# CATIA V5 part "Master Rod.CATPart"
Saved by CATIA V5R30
Part number: Master Rod
Bounding box of the stored display mesh (mm): x -55.99 to 55.99, y -51.999 to 267.322, z -35 to 35
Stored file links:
  D:\PROJECTS\CATIA V56R 2020\Resources\Parts File\c12_catia_v5_6r2020_prt\c12_catia_v5-6r2020 figr_12-26\Master Rod.CATPart
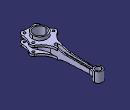
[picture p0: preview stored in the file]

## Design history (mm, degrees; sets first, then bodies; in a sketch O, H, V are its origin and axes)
Body1 (main body)
  Sketch1 on xy-plane, origin (0, 0, 0), H (1, 0, 0), V (0, 1, 0)
    arc A1 centre (0, 0) radius 31.5 from (-26.3425, 17.272) to (26.3425, 17.272) ccw
    arc A2 centre (0, 250) radius 17.5 from (14.7398, 240.5666) to (-14.7398, 240.5666) ccw
    point P1 (0, 250)
    line L1 (9, 220) -> (13, 60)
    point P2 (9, 220)
    point P3 (13, 60)
    arc A3 centre (94.6219, 62.0405) radius 81.6474 from (13, 60) to (26.3425, 17.272) ccw
    point P5 (26.3425, 17.272)
    arc A4 centre (45.4514, 220.9113) radius 36.4628 from (9, 220) to (14.7398, 240.5666) cw
    point P7 (14.7398, 240.5666)
    point P8 (-14.7398, 240.5666)
    point P9 (-9, 220)
    arc A5 centre (-45.4514, 220.9113) radius 36.4628 from (-9, 220) to (-14.7398, 240.5666) ccw
    point P11 (-13, 60)
    line L2 (-9, 220) -> (-13, 60)
    point P12 (-26.3425, 17.272)
    arc A6 centre (-94.6219, 62.0405) radius 81.6474 from (-13, 60) to (-26.3425, 17.272) cw
    radius A1 = 31.5
    radius A2 = 17.5
    distance P1 H = 250
    distance V P3 = 13
    distance P2 V = 9
    distance P1 P2 V = 30
    distance P3 P2 V = 160
    coincidence: P1 V
    tangency: A3 L1, A3 A1, A4 L1, A4 A2
    symmetry: P7 P8 V, P2 P9 V, A4 A5 V, P3 P11 V, L1 L2 V, P5 P12 V, A3 A6 V
  Pad1: profile Sketch1, direction (0, 0, 1), length 21, mirrored extent
  Sketch2 on face of Pad1, origin (0, 0, 21), H (1, 0, 0), V (0, 1, 0)
    point P1 (43, 16)
    point P2 (26, -39)
    arc A1 centre (43, 16) radius 13 from (53.3864, 8.1819) to (49.3111, 27.3653) ccw
    arc A2 centre (26, -39) radius 13 from (22.0235, -51.3769) to (38.9864, -38.4063) ccw
    reference projected line E1 (9, 220) -> (12.2872, 88.5122) from edge of Pad1
    arc A3 centre (84.2647, 90.3117) radius 72 from (49.3111, 27.3653) to (12.2872, 88.5122) cw
    point P5 (49.3111, 27.3653)
    point P6 (12.2872, 88.5122)
    arc A4 centre (110.9113, -35.118) radius 72 from (38.9864, -38.4063) to (53.3864, 8.1819) cw
    point P8 (38.9864, -38.4063)
    point P9 (53.3864, 8.1819)
    point P10 (-12.2872, 88.5122)
    point P11 (-49.3111, 27.3653)
    arc A5 centre (-84.2647, 90.3117) radius 72 from (-49.3111, 27.3653) to (-12.2872, 88.5122) ccw
    point P13 (-53.3864, 8.1819)
    arc A6 centre (-43, 16) radius 13 from (-53.3864, 8.1819) to (-49.3111, 27.3653) cw
    point P15 (-38.9864, -38.4063)
    arc A7 centre (-110.9113, -35.118) radius 72 from (-38.9864, -38.4063) to (-53.3864, 8.1819) ccw
    arc A8 centre (-26, -39) radius 13 from (-22.0235, -51.3769) to (-38.9864, -38.4063) cw
    line L1 (12.2872, 88.5122) -> (-12.2872, 88.5122)
    arc A9 centre (0, -119.9259) radius 72 from (-22.0235, -51.3769) to (22.0235, -51.3769) cw
    distance V P2 = 26
    distance P2 P1 H = 17
    distance P1 P2 V = 55
    distance P2 H = 39
    radius A1 = 13
    radius A2 = 13
    radius A3 = 72
    radius A4 = 72
    radius A9 = 72
    tangency: A3 E1, A3 A1, A4 A1, A4 A2, A9 A8, A9 A2
    symmetry: P6 P10 V, P5 P11 V, A3 A5 V, P9 P13 V, A1 A6 V, P8 P15 V, A4 A7 V, A2 A8 V
    horizontal: L1 H
  Pad2: profile Sketch2, direction (0, 0, -1), length 9
  Mirror1: of Pad2, Sketch2, about xy-plane
  Sketch3 on xy-plane, origin (0, 0, 0), H (1, 0, 0), V (0, 1, 0)
    circle A1 centre (0, 0) radius 31.5
    reference projected arc E1 centre (0, 0) radius 31.5 from (-26.3425, 17.272) to (26.3425, 17.272) ccw from edge of Pad2
    tangency: A1 E1
  Pad3: profile Sketch3, direction (0, 0, 1), length 35, mirrored extent
  Sketch4 on xy-plane, origin (0, 0, 0), H (1, 0, 0), V (0, 1, 0)
    circle A1 centre (0, 0) radius 26
    circle A2 centre (43, 16) radius 5
    circle A3 centre (26, -39) radius 5
    reference projected arc E1 centre (43, 16) radius 13 from (53.3864, 8.1819) to (49.3111, 27.3653) ccw from edge of Pad2
    reference projected arc E2 centre (26, -39) radius 13 from (22.0235, -51.3769) to (38.9864, -38.4063) ccw from edge of Pad2
    circle A4 centre (-26, -39) radius 5
    circle A5 centre (-43, 16) radius 5
    radius A1 = 26
    radius A3 = 5
    radius A2 = 5
    concentricity: A2 E1, A3 E2
    symmetry: A3 A4 V, A2 A5 V
  Pocket1: profile Sketch4, direction (0, 0, -1), length 35, mirrored extent
  Sketch5 on yz-plane, origin (0, 0, 0), H (0, 1, 0), V (0, 0, 1)
    line L1 (123.0834, 12) -> (250, 9)
    point P1 (123.0834, 12)
    point P2 (250, 9)
    arc A1 centre (124.9266, 89.9782) radius 78 from (88.5122, 21) to (123.0834, 12) ccw
    line L2 (88.5122, 21) -> (88.5122, 33.8539)
    line L3 (88.5122, 33.8539) -> (280.7471, 33.8539)
    line L4 (280.7471, 33.8539) -> (280.7471, 8.2732)
    point P8 (280.7471, 8.2732)
    line L5 (280.7471, 8.2732) -> (250, 9)
    distance P1 H = 12
    distance H P2 = 9
    distance V P2 = 250
    radius A1 = 78
    tangency: A1 L1, L5 A1
    vertical: L2 V, L4 V
    horizontal: L3 H
    coincidence: P8 L1
  Pocket2: profile Sketch5, direction (-1, 0, 0), length 35, mirrored extent
  Mirror2: of Pocket2, Sketch5, about xy-plane
  Sketch6 on xy-plane, origin (0, 0, 0), H (1, 0, 0), V (0, 1, 0)
    circle A1 centre (0, 250) radius 17.5
    point P1 (0, 250)
    reference projected arc E1 centre (0, 250) radius 17.5 from (17.5, 250) to (-17.5, 250) ccw from edge of Mirror2
    reference projected arc E2 centre (0, 250) radius 17.5 from (17.5, 250) to (-17.5, 250) ccw from edge of Mirror2
    coincidence: P1 V
    concentricity: E1 A1
    tangency: E2 A1
  Pad4: profile Sketch6, direction (0, 0, 1), length 21, mirrored extent
  Sketch7 on xy-plane, origin (0, 0, 0), H (1, 0, 0), V (0, 1, 0)
    circle A1 centre (0, 250) radius 12
    point P1 (0, 250)
    reference projected circle E1 centre (0, 250) radius 17.5 from edge of Pad4
    radius A1 = 12
    coincidence: P1 V
    concentricity: A1 E1
  Pocket3: profile Sketch7, direction (0, 0, -1), length 21, mirrored extent
  Sketch8 on xy-plane, origin (0, 0, 0), H (1, 0, 0), V (0, 1, 0)
    construction line L1 (0, 70) -> (0, 220)
    point P1 (0, 70)
    point P2 (0, 220)
    line L2 (-6, 70) -> (-6, 220)
    line L3 (6, 220) -> (6, 70)
    arc A1 centre (0, 220) radius 6 from (-6, 220) to (6, 220) cw
    arc A2 centre (0, 70) radius 6 from (6, 70) to (-6, 70) cw
    point P7 (0, 250)
    reference projected circle E1 centre (0, 250) radius 12 from edge of Pocket3
    length L1 = 150
    distance P7 P2 = 30
    radius A1 = 6
    coincidence: P1 V, P7 L1
    vertical: L1 V
    tangency: A1 L2, A2 L2, A1 L3, A2 L3
    parallelism: L1 L2
    concentricity: P7 E1
  Pocket4: profile Sketch8, direction (0, 0, 1), through (limit type 6), opposite side length -2.5
  Mirror3: of Pocket4, Sketch8, about xy-plane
